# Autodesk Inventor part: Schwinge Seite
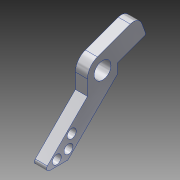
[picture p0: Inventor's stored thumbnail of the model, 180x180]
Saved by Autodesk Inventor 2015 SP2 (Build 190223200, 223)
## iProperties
Created: 2012-09
Part Number: Schwinge Seite
Material: Aluminium 6061
Document SubType Name: Modeling
Designer: rYan
Density: 2.71 g/cm^3
Mass: 13.5424 g
Surface Area: 33.3061 cm^2
Volume: 4.9972 cm^3
Appearance: Aluminium - flach
d0: 6,000 mm
d1: 45,00 grd
Author: rYan
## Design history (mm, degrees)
sketch "Skizze1"
  geometry: L1 (-8.485, 0)-(6.515, 15); L2 (16.515, 16.515)-(0, 0); L3 (0, 0)-(-8.485, 0); L4 (6.515, 15)-(6.515, 20); L5 (16.515, 16.515)-(16.515, 19.691); L6 (11.515, 20)-(30.919, 27.566); L7 (23.518, 29.69)-(25.912, 23.112); L8 (25.912, 23.112)-(16.515, 19.691); L9 (23.518, 29.69)-(9.805, 24.698); L10 (11.515, 18)-(33.266, 18); L11 (11.515, 20)-(11.515, 18); L12 (0, 35.627)-(0, -5.938) reference; L13 (-16.835, 0)-(41.616, 0) reference; A1 r 5 centre (11.515, 20) between (9.805, 24.698) and (6.515, 20)
  constraints: 22 end point, 3 point on line, 3 vertical, 2 horizontal, 2 parallel, 2 point on circle, 1 centre point, 1 perpendicular, 1 tangent
  dimensions: "d0" = 6 distance between parallel lines of L2 L1; "d1" = 45 deg angle of L3 L2; "d25" = 10 distance between parallel lines of L4 L5; "d29" = 5 distance of L1.end L4.end; "d36" = 2 distance from line of L6.start L10; "d37" = 2 distance from line of L6.start L8; "d38" = 5 radius of A1; "d40" = 10 distance of L7.end L5.end; "d57" = 20 deg angle of L13 L8; "d58" = 20 distance from line of L6.start L13
extrude "Extrusion1" new body sketch "Skizze1" distance "d4" = 4; taper "d5" = 0 deg
sketch "Skizze4"
  geometry: A1 r 5 centre (-11.515, -20) between (-9.805, -24.698) and (-6.515, -20) reference; 3 further points
  constraints: 2 coincident
hole "Bohrung1" sketch "Skizze4" at (-11.515, -20) diameter "d14" = 5.6; stored, may be unused: countersink angle "d18" = 90 deg, drill point angle "d20" = 118 deg; dims "d15" = 6, "d16" = 4, "d17" = 2, "d19" = 8
fillet "Rundung1" dims "d21" = 1
fillet "Rundung2" dims "d41" = 3
fillet "Rundung3" dims "d42" = 0.5
sketch "Skizze5"
  geometry: L1 (6.95, 1.293)-(2, -3.657); L2 (4.475, -1.182)-(3.061, 0.232); L3 (15, 6.515)-(1.707, -6.778) reference; L4 (0, -6.071)-(0, 0) reference; 3 further points
  constraints: 4 end point, 3 coincident, 1 midpoint, 1 parallel, 1 perpendicular
  dimensions: "d45" = 7 distance of L1.start L1.end; "d46" = 2 distance of L2.start L2.end; "d48" = 2 distance between parallel lines of L3 L1; "d49" = 2 distance from line of L4 point (2, -3.657)
hole "Bohrung2" sketch "Skizze5" at (6.95, 1.293), (2, -3.657), (3.061, 0.232) diameter "d50" = 3; stored, may be unused: countersink angle "d54" = 90 deg, drill point angle "d56" = 118 deg; dims "d51" = 6, "d52" = 4, "d53" = 2, "d55" = 8
node "Volumenkörper1"
other parameters: "d22" = 5
